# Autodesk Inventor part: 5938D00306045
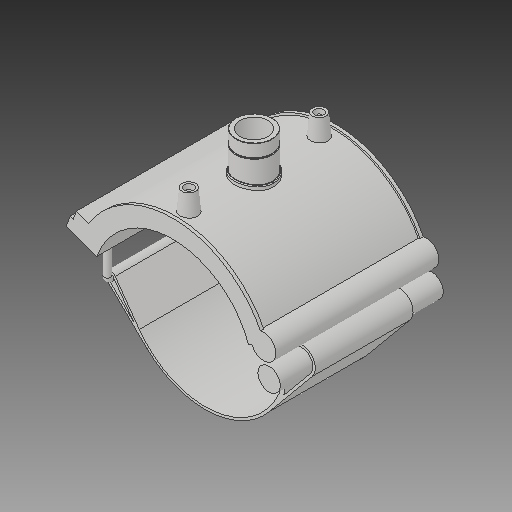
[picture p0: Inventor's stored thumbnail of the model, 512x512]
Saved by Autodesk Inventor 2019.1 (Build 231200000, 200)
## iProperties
Created: 2017-07
Part Number: 5938D00306045
Material: Generic
Description: PLASSON TRANSITION SADDLE 6''DIPS x 1"NPT
Document SubType Name: Modeling
Designer: KIM
Density: 1 g/cm^3
Appearance: Default
Author: KIM
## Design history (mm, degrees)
derived "5938D.ipt"
feature "Solid1::5938D.ipt"
tag "TaggingFeature1"
body "Solid1"
other parameters: "d_" = 174.5, "B_" = 176.784, "H_" = 41.91, "L_" = 176.022, "d_t" = 6, "G_" = 30.291, "d148" = 2.6175, "d160" = 2.6175, "d169" = 2.6175, "d192" = 6.98, "d0" = 174.5, "d1" = 209.4, "d2" = 441.96, "d3" = 43.625, "d4" = 176.022, "d5" = 0, "d40" = 108.888, "d41" = 42.4074, "d43" = 0, "d45" = 0, "d47" = 146.61, "d48" = 39.3783, "d50" = 0, "d78" = 126.7, "d79" = 15, "d80" = 70.4088, "d82" = 5 deg, "d84" = 4, "d85" = 14, "d86" = 0, "d87" = 3, "d88" = 0, "d96" = 213.588, "d97" = 3.52044, "d98" = 0, "d102" = 0.90873, "d103" = 30.291, "d104" = 25.146, "d105" = 0, "d106" = 24.2328, "d108" = 0, "d109" = -13.97, "d111" = 0.5, "d112" = 0.5, "d113" = 0, "d114" = 0.5, "d117" = 0.30291, "d120" = 140 deg, "d121" = 24.228, "d122" = 20 deg, "d123" = 837.6, "d124" = 125.64, "d126" = 0, "d143" = 179.735, "d145" = 26.84615, "d149" = 2.6175, "d150" = 29.53077, "d153" = 176.022, "d154" = 0, "d156" = 104.7, "d157" = 160 deg, "d159" = 6.98, "d161" = 2.6175, "d162" = 105.6132, "d163" = 0, "d164" = 87.25, "d167" = 17.45, "d168" = 102.14634, "d170" = 2.6175, "d172" = 0, "d173" = 1, "d175" = 87.25, "d176" = 20 deg, "d177" = 12.215, "d178" = 34.9, "d180" = 0, "d183" = 13.96, "d184" = 9.772, "d185" = 57.20715, "d186" = 57.20715, "d187" = 104.7, "d188" = 10.47, "d189" = 12.215, "d190" = 0, "d191" = 125.64, "d193" = 6.98, "d194" = 3.57725, "d195" = 90 deg, "d197" = 0, "d199" = 0
